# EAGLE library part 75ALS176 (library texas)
DIFFERENTIAL BUS TRANSCEIVERS TIA/EIA-422-B, TIA/EIA-422-B + TIA/EIA-422-B TIA/EIA-422-B Operate at Data Rates up to 35 Mbaud Source: http://focus.ti.com/lit/ds/symlink/sn65als176.pdf
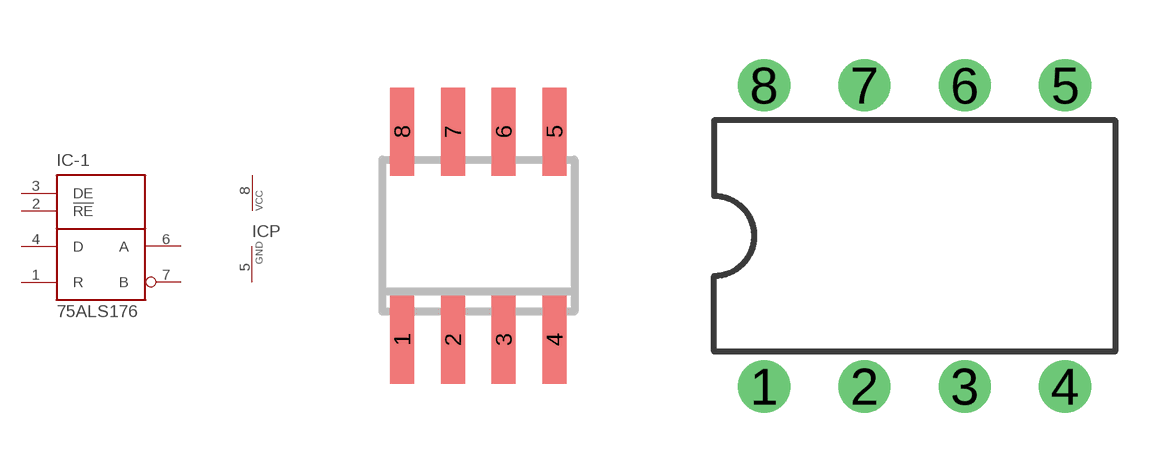
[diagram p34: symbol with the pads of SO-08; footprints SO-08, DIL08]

Designator prefix IC; gates -1=75ALS176 P=VCCGND

## 75ALS176D (MF: TEXAS INSTRUMENTS; MPN: SN75ALS176D; OC_FARNELL: 9593020; OC_NEWARK: 08F8011), 75ALS176AD (MF: TEXAS INSTRUMENTS; MPN: SN75ALS176AD; OC_FARNELL: 1410742; OC_NEWARK: 76C5099), 75ALS176BD (MF: TEXAS INSTRUMENTS; MPN: SN75ALS176BD; OC_FARNELL: 9593012; OC_NEWARK: 35K0833)  [SO-08]
1  -1:R  out
2  -1:!RE  in
3  -1:DE  in
4  -1:D  in
5  P:GND  pwr
6  -1:A
7  -1:B
8  P:VCC  pwr

## 75ALS176P (MF: TEXAS INSTRUMENTS; MPN: SN75ALS176P; OC_FARNELL: 1103021; OC_NEWARK: 60K6915)  [DIL08]
Pads as for SO-08

## Footprint SO-08 (pad centres in mm)
D (R-PDSO-G8) Plastic Small Outline Package Source: http://focus.ti.com/lit/ds/symlink/sn65als176.pdf
smd 0.6 x 2.2: 1 -1.905,-2.6; 2 -0.635,-2.6; 3 0.635,-2.6; 4 1.905,-2.6; 5 1.905,2.6; 6 0.635,2.6; 7 -0.635,2.6; 8 -1.905,2.6

## Footprint DIL08 (pad centres in mm)
Dual In Line Package
drill 0.813 pad 1.27 round: 1 -3.81,-3.81; 2 -1.27,-3.81; 3 1.27,-3.81; 4 3.81,-3.81; 5 3.81,3.81; 6 1.27,3.81; 7 -1.27,3.81; 8 -3.81,3.81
